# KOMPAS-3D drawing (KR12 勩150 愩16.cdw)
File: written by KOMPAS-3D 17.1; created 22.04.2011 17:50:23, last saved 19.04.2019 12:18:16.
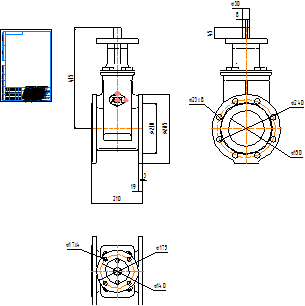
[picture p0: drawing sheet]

Title block, sheet 1: name: KR12 Ду150 Ру16; material: Внимание! Данный продукт является объектом авторского права ООО «Торговый Дом АДЛ». / Запрещается изменение, копирование, распространение / (в том числе путем копирования на другие сайты и ресурсы в Интернете) / или любое иное использование информации и объектов без предварительного / согласия правообладателя (ООО «Торговый Дом АДЛ»).; scale: 1:1; sheets: 1; organisation: ООО "Торговый дом АДЛ"; sheet format: A4; stored path: \\adlc.lan\data\АДЛ_ПКД\3D-модели\ADL production\Клиновые задвижки серии KR ГРАНАР\Клиновые задвижки KR12\KOMPAS 2D\KR12 Ду150 Ру16.cdw

Views: Спереди 7, Проекционный вид 8, Проекционный вид 9
Dimensions and other numbers on the sheet: 285; 210; 415; 19; 3; 175; 17; 140; 30; 45; 8; 23; 240; 150; 1:1; 1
